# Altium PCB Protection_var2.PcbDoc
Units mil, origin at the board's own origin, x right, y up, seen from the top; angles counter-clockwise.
Board outline 2400 x 1600 mil, 2 copper layers (Top Layer, Bottom Layer), stack 62 mil thick; 54 components, 17 nets, 103 pads, 31 vias.
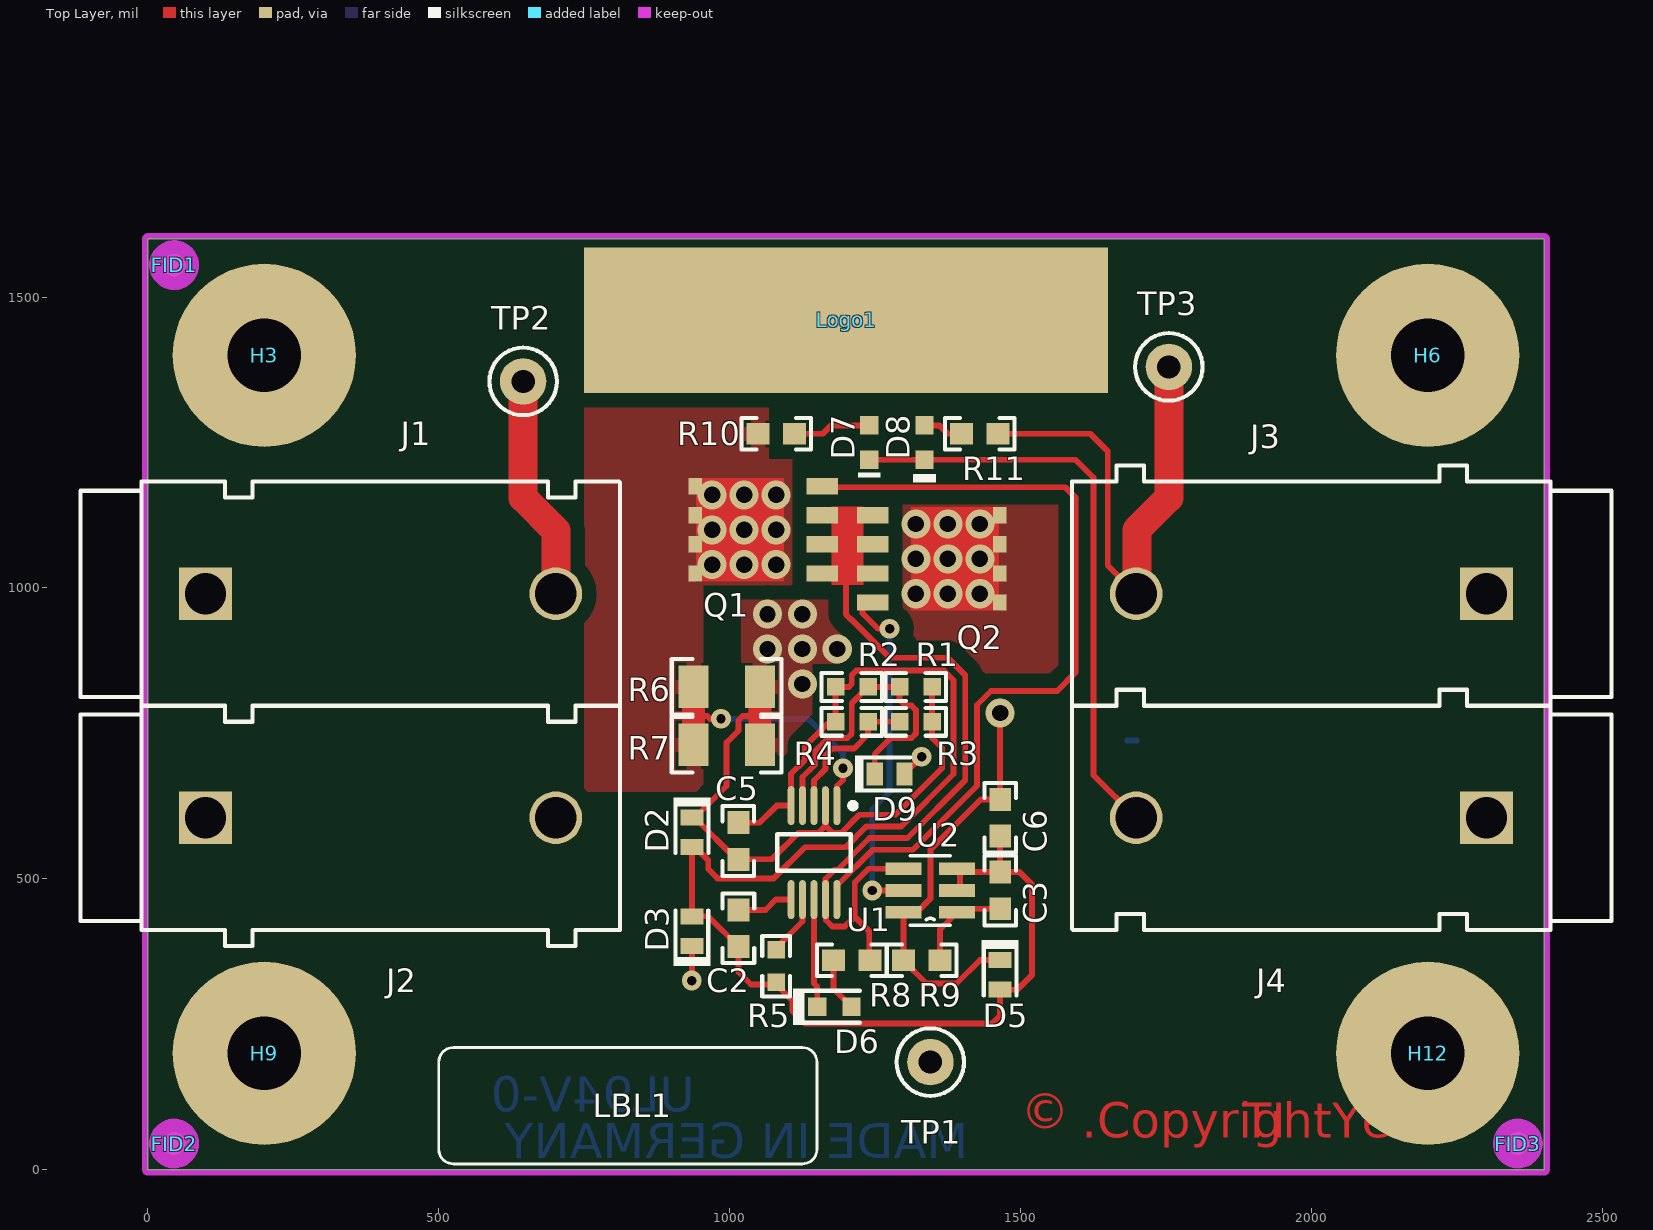
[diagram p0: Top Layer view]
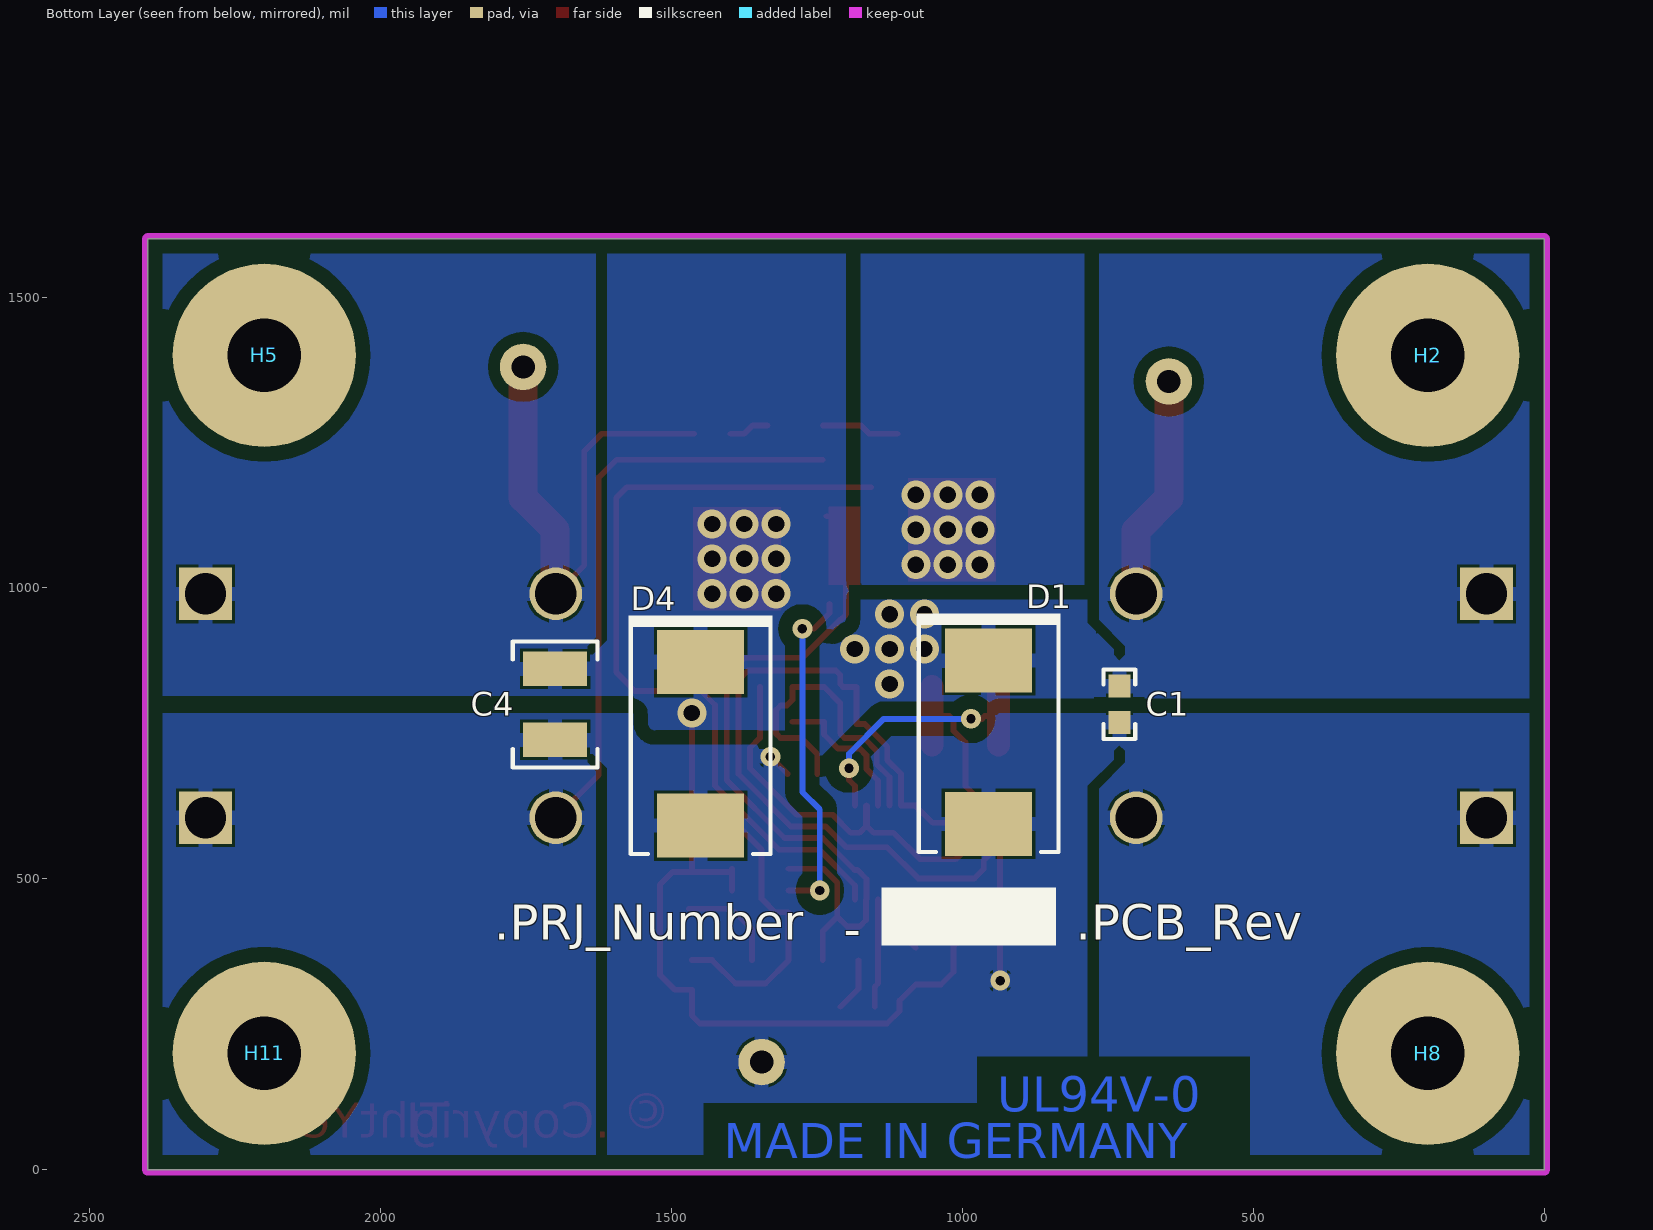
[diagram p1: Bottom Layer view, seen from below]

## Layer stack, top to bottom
Top Layer: signal copper 1.4
Dielectric: core 59.2, FR-4, Dk 4.8
Bottom Layer: signal copper 1.4

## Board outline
0,0 2400,0 2400,1600 0,1600

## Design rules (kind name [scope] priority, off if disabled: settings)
AcuteAngle [All] p1: minimum=4.50000000000000E+0001 checktracksonly=FALSE
AssemblyTestPointUsage [All] p1: valid=2
Clearance Clearance_BoardEdge_MountingHoles [OnCopper and InComponentClass('Mounting Holes') vs IsKeepOut] p1: gap=40
Clearance Clearance_BoardEdge_Poly [OnCopper and InPoly vs IsKeepOut] p2: gap=25
Clearance Clearance_BoardEdge [OnCopper and Not InComponentClass('Logo') and not InComponentClass('FiducialMark') and not InRegion(1000,500,4000,800) and Not IsKeepout vs IsKeepOut] p3: gap=75
Clearance Clearance_Poly [InPolygon] p4: gap=25
Clearance [All] p5: gap=8
ComponentClearance ComponentClearance_Shunt [InComponentClass('Header') vs InComponentClass('Shunt')] p1: gap=0 collisioncheckmode=3 verticalgap=0 showdistances=FALSE
ComponentClearance ComponentClearance_Logo [InComponentClass('Logo')] p2: gap=50 collisioncheckmode=3 verticalgap=10 showdistances=FALSE
ComponentClearance ComponentClearance_ScrewToNut [(HasFootprint('NY PMS 440 0025 PH')) vs (HasFootprint('Keystone_1902C'))] p3: gap=5 collisioncheckmode=3 verticalgap=10 showdistances=FALSE
ComponentClearance ComponentClearance_MountingHoles [InComponentClass('Mounting Holes')] p4: gap=250 collisioncheckmode=3 verticalgap=100000 showdistances=FALSE
ComponentClearance ComponentClearance_SmallPassives [HasFootprint('0201*') or HasFootprint('0402*') or HasFootprint('0508') or HasFootprint('0603*') or HasFootprint('0612') or HasFootprint('0805*') or HasFootprint('0815*') or HasFootprint('0830*') or HasFootprint('1206*') or HasFootprint('1210*') or HasFootprint('1808*') or HasFootprint('1812*') or HasFootprint('1825*') or HasFootprint('2010*') or HasFootprint('2220*') or HasFootprint('2225*') or HasFootprint('2512*') or HasFootprint('2728*') or HasFootprint('3518*') vs HasFootprint('0201*') or HasFootprint('0402*') or HasFootprint('0508') or HasFootprint('0603*') or HasFootprint('0612') or HasFootprint('0805*') or HasFootprint('0815*') or HasFootprint('0830*') or HasFootprint('1206*') or HasFootprint('1210*') or HasFootprint('1808*') or HasFootprint('1812*') or HasFootprint('1825*') or HasFootprint('2010*') or HasFootprint('2220*') or HasFootprint('2225*') or HasFootprint('2512*') or HasFootprint('2728*') or HasFootprint('3518*')] p5: gap=20 collisioncheckmode=3 verticalgap=10 showdistances=FALSE
ComponentClearance ComponentClearance_THtoSMT [IsThruComponent vs IsSMTComponent] p6: gap=100 collisioncheckmode=3 verticalgap=30 showdistances=FALSE
ComponentClearance ComponentClearance_THtoTH [IsThruComponent vs IsThruComponent] p7: gap=118.11 collisioncheckmode=3 verticalgap=30 showdistances=FALSE
ComponentClearance [All] p8: gap=40 collisioncheckmode=3 verticalgap=10 showdistances=FALSE
DiffPairsRouting [All] p1: maxlimit=100 minlimit=10 mostfreqgap=10 maxuncoupledlength=1000
FabricationTestPointUsage TestPointUsage [All] p1: valid=2 allowmultiple=FALSE
FabricationTestpoint Testpoint [All] p1: side=3 testpointundercomponent=TRUE minsize=40 maxsize=100 preferedsize=60 minholesize=0 maxholesize=40 preferedholesize=32 testpointgrid=1 allowsidetop=TRUE allowsidebottom=TRUE usegrid=TRUE gridtolerance=0.01
FanoutControl Fanout_LCC [IsLCC] p1: bgadir=Out bgaviamode=Centered fanoutstyle=Auto fanoutdirection=Alternating viagrid=1 // Fanout_LCC (Default Rule)
FanoutControl Fanout_BGA [IsBGA] p2: bgadir=Out bgaviamode=Centered fanoutstyle=Auto fanoutdirection=Alternating viagrid=1 // Fanout_BGA (Default Rule)
FanoutControl Fanout_Default [All] p4: bgadir=Out bgaviamode=Centered fanoutstyle=Auto fanoutdirection=Alternating viagrid=1 // Fanout_Default (Default Rule)
FanoutControl Fanout_Small [(CompPinCount < 5)] p5: bgadir=Out bgaviamode=Centered fanoutstyle=Auto fanoutdirection=OutThenIn viagrid=1 // Fanout_Small (Default Rule)
HoleSize [All] p1: absolutevalues=TRUE maxlimit=251 minlimit=8 maxpercent=80.000 minpercent=20.000
MinimumAnnularRing MinimumAnnularRing_ThermalPadVias [IsVia and InAnyComponent] p1: minimumring=5.91
MinimumAnnularRing [All] p2: minimumring=9
MinimumSolderMaskSliver MinimumSolderMaskSliver_Logo [InComponentClass('Logo') vs InComponentClass('Logo')] p1: minsoldermaskwidth=0.7
MinimumSolderMaskSliver [All] p2: minsoldermaskwidth=3.94
PlaneConnect [All] p1: planeconnectstyle=Relief reliefexpansion=10 reliefentries=4 reliefconductorwidth=10 reliefairgap=10
PolygonConnect ThermalPolygonQ [(ObjectKind = 'Pad') And (Name Like 'Q*')] p1: connectstyle=Direct reliefconductorwidth=10 reliefentries=4 polygonreliefangle="90 Angle" airgapwidth=10 // Connect Transistor Cooling Pad to Poligon
PolygonConnect ThermalPolygonVia [(ObjectKind = 'Via') And (ViaDiameter = '50')] p2: connectstyle=Direct reliefconductorwidth=10 reliefentries=4 polygonreliefangle="90 Angle" airgapwidth=10
PolygonConnect [All] p3: connectstyle=Relief reliefconductorwidth=25 reliefentries=4 polygonreliefangle="90 Angle" airgapwidth=5
RoutingVias ThermalPadVias [IsVia and InAnyComponent] p1: holewidth=7.87 width=19.68 viastyle="Through Hole" minholewidth=7.87 minwidth=19.68 maxholewidth=12.99 maxwidth=23.62
RoutingVias [All] p2: holewidth=16 width=34 viastyle="Through Hole" minholewidth=7.87 minwidth=26 maxholewidth=40 maxwidth=65
SMDToCorner [All] p1: distance=30000
SilkToSilkClearance [All] p1: silktosilkclearance=5
SilkscreenOverComponentPads [All] p1: minsilkscreentomaskgap=5
SolderMaskExpansion [All] p1: expansion=1.97
Width [All] p1: maxlimit=100 minlimit=6 preferedwidth=10 checkconnectedcopper=TRUE
14 further rules are at their usual default settings.

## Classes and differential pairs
component class Label: LBL1
component class AssemblyNote: ZZ1 ZZ2 ZZ3 ZZ4
component class FiducialMark: FID1 FID2 FID3
component class "Pg4 Hardware": FID1 FID2 FID3 H2 H3 H5 H6 H8 H9 H11 H12 LBL1 Logo1 ZZ1 ZZ2 ZZ3 ZZ4
component class Logo: Logo1
component class "Mounting Holes": H3 H6 H9 H12
component class "Pg3 Protection": C1 C2 C3 C4 C5 C6 D1 D2 D3 D4 D5 D6 D7 D8 D9 J1 J2 J3 J4 Q1 Q2 R1 R2 R3 R4 R5 R6 R7 R8 R9 R10 R11 TP1 TP2 TP3 U1 U2

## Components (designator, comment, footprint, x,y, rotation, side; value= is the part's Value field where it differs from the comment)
C1 "06031C102JAT2A" 0603 730,800 r270 bottom
C2 "UMK107ABJ474KA-T" 0603 1015,415 r270 top
C3 "GRM188R72A104KA35D" 0603 1465,480 r90 top
C4 "C3225X7S2A475K200AB" 1210M 1700,800 r270 bottom
C5 "GRM188R72A104KA35D" 0603 1015,565 r90 top
C6 "GRM188R72A104KA35D" 0603 1465,605 r270 top
D1 "SMCJ33CA" SMC 955,735 r270 bottom
D2 "CD0603-S01575" Diode_0603 935,580 r270 top
D3 "CD0603-S01575" Diode_0603 935,410 r90 top
D4 "SMCJ33CA" SMC 1450,731.97 r270 bottom
D5 "CD0603-S01575" Diode_0603 1465,335 r270 top
D6 "LTST-C190CKT" LED_LTST-C190_Red 1180,280 r180 top
D7 "LB Q39G-L2N2-35-1" "LB Q39G_BLUE" 1240,1250 r270 top
D8 "LTST-C190KGKT" LED_LTST-C190_G 1335,1250 r270 top
D9 "CD0603-S01575" Diode_0603 1275,680 r0 top
FID1 "Fiducial" Fiducial10-20 45,1555 r0 top
FID2 "Fiducial" Fiducial10-20 45,45 r0 top
FID3 "Fiducial" Fiducial10-20 2355,45 r0 top
H2 "1902C" Keystone_1902C 200,1400 r180 bottom locked
H3 "NY PMS 440 0025 PH" "NY PMS 440 0025 PH" 200,1400 r0 top locked
H5 "1902C" Keystone_1902C 2200,1400 r180 bottom locked
H6 "NY PMS 440 0025 PH" "NY PMS 440 0025 PH" 2200,1400 r0 top locked
H8 "1902C" Keystone_1902C 200,200 r180 bottom locked
H9 "NY PMS 440 0025 PH" "NY PMS 440 0025 PH" 200,200 r0 top locked
H11 "1902C" Keystone_1902C 2200,200 r180 bottom locked
H12 "NY PMS 440 0025 PH" "NY PMS 440 0025 PH" 2200,200 r0 top locked
J1 "571-0500" 571-0500 400,990 r0 top
J2 "571-0100" 571-0100 400,605 r0 top
J3 "571-0500" 571-0500 2000,990 r180 top
J4 "571-0100" 571-0100 2000,605 r180 top
LBL1 "Size: 0.65\" x 0.20 \"" Label_650x200 825,110 r0 top
Logo1 "Texas Instruments" TI_Stacked_SolderMask_Small 1200,1460 r0 top
Q1 "CSD18532Q5B" TRANS_NexFET_Q5B 1050,1100 r180 top
Q2 "CSD18532Q5B" TRANS_NexFET_Q5B 1355,1050 r0 top
R1 "CRCW060395K3FKEA" 0603_HV 1320.08,830 r0 top
R2 "CRCW06038K06FKEA" 0603_HV 1210,830 r0 top
R3 "CRCW060347K5FKEA" 0603_HV 1320.08,770 r0 top
R4 "CRCW060314K0FKEA" 0603_HV 1210,770 r0 top
R5 "CRCW060357K6FKEA" 0603_HV 1080,350 r90 top
R6 "WSLP1206R0100FEA" 1206 995,830 r180 top
R7 "WSLP1206R0100FEA" 1206 995,730.2 r180 top
R8 "CRCW060310K0FKEA" 0603 1210,360 r180 top
R9 "CRCW0603100RFKEA" 0603 1330,360 r180 top
R10 "CRCW060310K0FKEA" 0603 1080,1265 r0 top
R11 "CRCW060310K0FKEA" 0603 1430,1265 r180 top
TP1 "5001" Keystone5001 1345,185 r0 top
TP2 "5000" Keystone5000 645,1355 r0 top
TP3 "5000" Keystone5000 1755,1380 r0 top
U1 "LM5069MM-2/NOPB" MUB10A_N 1145,545.12 r270 top
U2 "LM5050MK-1/NOPB" DDC0006A_N 1345,480 r180 top
ZZ1 "This Assembly Note is for PCB labels only" AssemblyNoteLabel -10,3268 r0 top
ZZ2 "These assemblies are ESD sensitive, ESD precautions shall be observed." AssemblyNote -10,3159.11 r0 top
ZZ3 "These assemblies must be clean and free from flux and all contaminants. Use of no clean flux is not acceptable." AssemblyNote -10,3070.56 r0 top
ZZ4 "These assemblies must comply with workmanship standards IPC-A-610 Class 2, unless otherwise specified." AssemblyNote -10,2982 r0 top

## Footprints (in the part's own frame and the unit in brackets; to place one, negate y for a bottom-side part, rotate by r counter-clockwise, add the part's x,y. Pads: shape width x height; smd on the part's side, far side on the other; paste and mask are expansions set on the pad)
571-0100 [mm] "Deltron Emcon recommended land pattern 2003-10-13"
  rect 2.3x2.3 hole 1.8: 1(-7.65,0)
  round 2.3 hole 1.8: 2(7.65,0)
  silkscreen extent -13.1,-5.6 10.45,4.9, body extent -13.04,-5.6 10.54,4.9, height 12.4
571-0500 [mm] "Deltron Emcon recommended land pattern 2003-10-13"
  rect 2.3x2.3 hole 1.8: 1(-7.65,0)
  round 2.3 hole 1.8: 2(7.65,0)
  silkscreen extent -13.1,-5.6 10.45,4.9, body extent -13.04,-5.6 10.54,4.9, height 12.4
0603 [mm] "0603 from SM-752 data"
  rect 1x0.95 smd: 1(-0.8,0) 2(0.8,0)
  silkscreen extent -1.52,-0.69 1.52,0.69, body extent -0.87,-0.47 0.87,0.47, height 0.85
0603_HV [mil] "Ernesto recommended land pattern.  26 mil between pads."
  rect 30x30 smd: 1(-28,0) 2(28,0)
  silkscreen extent -52,-24 52,24, body extent -34,-19 34,19, height 33
1206 [mm] "1206 from SM-752 data"
  rect 1.3x1.85 smd: 1(-1.45,0) 2(1.45,0)
  silkscreen extent -2.4,-1.21 2.4,1.21, body extent -1.7,-0.9 1.7,0.9, height 1.35
1210M [mm] "1210 from SM-752 data"
  rect 1.5x2.8 smd: 1(-1.55,0) 2(1.55,0)
  silkscreen extent -2.75,-1.85 2.75,1.85, body extent -1.7,-1.35 1.7,1.35, height 1.35
AssemblyNote [mil] "Assembly Note"
AssemblyNoteLabel [mil] "Assembly Note for PCB Labels"
DDC0006A_N [mil]
  rect 62x22 smd: 1(-46,37.4) 2(-46,0) 3(-46,-37.4) 4(46,-37.4) 5(46,0) 6(46,37.4)
  silkscreen extent -35,-60 35,60, body extent -56,-58 56,58, height 35
Diode_0603 [mm] "Based on Bourns recommended land pattern Rev 10/09"
  rect 0.7x1 smd: 1(-0.65,0) 2(0.65,0)
  silkscreen extent -1.5,-0.8 0.9,0.8, body extent -0.9,-0.5 0.9,0.5, height 0.85
Fiducial10-20 [mm]
  round 1 smd paste-0.5 mask+0.5: 1(0,0)
  Top Layer keep-out circle w1.178: c0,0 r0.5
Keystone5000 [mil] "For Keystone 500x miniature loop terminals"
  round 80 hole 40: 1(0,0)
  silkscreen extent -58,-58 58,58, body extent -49,-49 49,49, height 182
Keystone5001 [mil] "For Keystone 500x miniature loop terminals"
  round 80 hole 40: 1(0,0)
  silkscreen extent -58,-58 58,58, body extent -49,-49 49,49, height 182
Keystone_1902C [mil] "Hex Standoff, 4-40 threaded, nylon"
  body extent -145,-126 146,126, height 501
Label_650x200 [mil] "Thermal Transfer Label"
  silkscreen extent -325,-100 325,100, body extent -326,-101 326,101, height 1
"LB Q39G_BLUE" [mm] "OSRAM"
  rect 0.8x0.8 smd: 1(-0.75,0) 2(0.75,0)
  silkscreen extent 1.31,-0.5 1.53,0.5, body extent -0.85,-0.45 0.85,0.45, height 0.4
LED_LTST-C190_G [mm] "Lite-On"
  rect 0.8x0.8 smd: 1(-0.75,0) 2(0.75,0)
  silkscreen extent 1.37,-0.5 1.75,0.5, body extent -0.85,-0.45 0.85,0.45, height 0.9
LED_LTST-C190_Red [mm] "Lite-On"
  rect 0.8x0.8 smd: 1(-0.75,0) 2(0.75,0)
  silkscreen extent -1.1,-0.8 1.8,0.8, body extent -0.85,-0.45 0.85,0.45, height 0.9
MUB10A_N [mm] "TSSOP, 10-Leads, Body 3x3mm, Pitch 0.5mm, IPC Medium Density"
  oval 1.7x0.3 smd: 1(-2.05,1) 2(-2.05,0.5) 3(-2.05,0) 4(-2.05,-0.5) 5(-2.05,-1) 6(2.05,-1) 7(2.05,-0.5) 8(2.05,0) 9(2.05,0.5) 10(2.05,1)
  silkscreen extent -2.17,-1.6 0.8,1.83, body extent -1.6,-1.6 1.6,1.6, height 1.09
"NY PMS 440 0025 PH" [mm] "4-40 nylon screw and mounting hole"
  round 8 hole 3.2: 1(0,0)
  body extent -3.3,-3.3 3.3,3.3, height 2.69
SMC [mil] "Molded Diode, 2-Leads, Body 6.9x5.8mm, IPC Medium Density, based on OnSemi component dimensions and land patterns"
  rect 110x150 smd: 1(-140.49,0) 2(140.49,0)
  silkscreen extent -221,-124 189,123, body extent -156,-116 156,116, height 91
TI_Stacked_SolderMask_Small [mil]
  rect 900x250 smd paste-125 mask-125: 0(0,0)
TRANS_NexFET_Q5B [mm] "TI recommended land pattern (nominal) November 2012"
  rect 1.372x0.71 smd paste-0.4 mask+0.051: 1(-2.776,1.905) 2(-2.776,0.635) 3(-2.776,-0.635) 4(-2.776,-1.905)
  rect 0.59x0.71 smd paste-0.3: 5(2.776,-1.905) 6(2.776,-0.635) 7(2.776,0.635) 8(2.776,1.905)
  Top Layer region: -1.106,-2.26 2.744,-2.26 2.744,2.26 -1.106,2.26
  body extent -3.23,-2.55 2.87,2.55, height 1.06

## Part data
C1: "CAP, CERM, 1000pF, 100V, +/-5%, X7R, 0603"
C2: "CAP, CERM, 0.47uF, 50V, 10%, X5R, 0603"
C3 C5 C6: "CAP, CERM, 0.1uF, 100V, +/-10%, X7R, 0603"
C4: "CAP, CERM, 4.7uF, 100V, +/-10%, X7S, 1210"
D1 D4: "Diode, TVS, Bi, 33V, 1500W, SMC"
D2 D3 D5 D9: "Diode, Switching, 100V, 0.15A, 0603 Diode"
D6: "LED, Red, SMD"
D7: "LED, Blue, SMD"
D8: "LED, Green, SMD"
FID1 FID2 FID3: "Fiducial mark.  There is nothing to buy or mount."
H2 H5 H8 H11: "Standoff, Hex, 0.5\"L #4-40 Nylon"
H3 H6 H9 H12: "Machine Screw, Round, #4-40 x 1/4, Nylon, Philips panhead"
J1 J3: "Standard Banana Jack, insulated, 10A, red"
J2 J4: "Standard Banana Jack, insulated, 10A, black"
LBL1: library part THT-14-423-10, "Thermal Transfer Printable Labels, 0.650\" W x 0.200\" H - 10,000 per roll"
Logo1: library part TI_Logo, "Texas Instrument Corporate Signature"
Q1 Q2: "MOSFET, N-CH, 60V, 172A, SON 5x6mm"
R1: "RES, 95.3k ohm, 1%, 0.1W, 0603"
R2: "RES, 8.06k ohm, 1%, 0.1W, 0603"
R3: "RES, 47.5k ohm, 1%, 0.1W, 0603"
R4: "RES, 14.0k ohm, 1%, 0.1W, 0603"
R5: "RES, 57.6k ohm, 1%, 0.1W, 0603"
R6 R7: "RES, 0.01 ohm, 1%, 1W, 1206"
R8 R10 R11: "RES, 10.0k ohm, 1%, 0.1W, 0603"
R9: "RES, 100 ohm, 1%, 0.1W, 0603"
TP1: "Test Point, Miniature, Black, TH"
TP2 TP3: "Test Point, Miniature, Red, TH"
U1: "Positive High Voltage Hot Swap / Inrush Current Controller with Power Limiting, 10-pin MSOP, Pb-Free"
U2: "LM5050-1 High Side OR-ing FET Controller, DDC0006A"
ZZ1: library part AssemblyNoteLabel
ZZ2 ZZ3 ZZ4: library part AssemblyNote

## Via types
v1: diameter 50, hole 28, Top Layer to Bottom Layer, 25 vias
v2: diameter 34, hole 16, Top Layer to Bottom Layer, 6 vias

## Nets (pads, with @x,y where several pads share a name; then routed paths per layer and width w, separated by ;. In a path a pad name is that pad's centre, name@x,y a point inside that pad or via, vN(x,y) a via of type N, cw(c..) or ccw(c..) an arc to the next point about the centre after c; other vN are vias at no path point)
24V_LIM: C4.1 C6.1 D4.1 D5.1 J3.1 J3.2 Q2.5 Q2.6 Q2.7 Q2.8 R9.2 R11.1 TP3.1 U2.6 | length 1791.1
  Top Layer w10: R11.1 1620.05,1265 1650,1235.05 1650,1038.82 J3.2 ; D5.1 1430.59,360.59 1390,320 1338.5,320 R9.2 1299,360.5 U2.6 1321.98,442.6 1345,465.62 1345,550 1431.5,636.5 C6.1 v1(1465,785)
  Top Layer w50: J3.2@1700,995 1700,1100 1755,1155 TP3.1
  Bottom Layer w10: J3.2 J3.2@1700,988.82 ; TP3.1@1785,1380 ccw(c1755,1380) TP3.1@1785,1380
  other v1: 1320,990 1375,990 1430,990 1320,1050 1375,1050 1430,1050 1320,1110 1375,1110 1430,1110
+24V: C1.1 C5.1 D1.1 D2.1 J1.1 J1.2 R1.2 R3.2 R6.1 R7.1 TP2.1 U1.2 | length 1665.3
  Top Layer w10: D2.1 939.41,605.59 1011.5,533.5 C5.1 1072.36,533.5 1118.22,579.36 1152.83,579.36 1163.91,590.44 1163.91,625.05 U1.2 1165.46,625.05 1165.46,590.44 1176.54,579.36 1192.2,579.36 1222.84,610 1285,610 1365,690 1365,725 1348.08,741.92 R3.2 R1.2 ; D2.1@940.59,605.59 994.41,659.41 994.41,734.08 1015,754.67 1015,772.57 1022.52,780.1 1052.09,780.1
  Top Layer w40: R7.1 1052.09,780.1 R6.1
  Top Layer w50: TP2.1 645,1155 701.18,1098.82 J1.2
  Bottom Layer w10: TP2.1@675,1355 ccw(c645,1355) TP2.1@675,1355
  other v1: 1125,835 1065,895 1125,895 1185,895 1065,955 1125,955
GND: C1.2 C4.2 D1.2 D3.1 D4.2 D7.2 D8.2 D9.2 J2.1 J2.2 J4.1 J4.2 TP1.1 | length 1131.9
  Top Layer w10: v2(935,325) D3.1 ; D7.2 D8.2 1594.53,1220.47 1625.2,1189.8 1625.2,678.62 J4.2 ; D9.2 1300.59,680.59 v2(1330,710)
  Bottom Layer w10: C4.2@1682.91,737.91 C4.2@1700,737.91
NetC2_1: C2.1 U1.6 | length 98.1
  Top Layer w10: C2.1 1061.5,446.5 1079.41,464.41 U1.6
NetC2_2: C2.2 C3.2 C5.2 C6.2 D2.2 D3.2 D5.2 R2.1 R4.1 R5.1 U1.5 U2.2 U2.3 | length 2553.8
  Top Layer w10: D3.2 962.91,435.59 C2.2 1015,340 1036.5,318.5 1080,318.5 1107.82,290.68 1107.82,272.77 1129.34,251.25 1451.25,251.25 1465,265 D5.2 1494.41,309.41 1520,335 1520,490 1498.5,511.5 C3.2 ; D3.2@935,440.71 D2.2 940.59,554.41 963.06,531.94 963.06,516.94 979.18,500.82 1075.82,500.82 1129.41,554.41 1199.41,554.41 1235,590 1295,590 1385,680 1385,841.46 1368.46,858 1217.62,858 1210,850.38 1210,835 1205,830 R2.1 R4.1 1182,766 1167.66,766 1129,727.34 1129,704 1105.63,680.63 U1.5 1080.83,625.83 1051.5,596.5 C5.2 ; U2.2@1396,480 U2.3@1396,510 ; U2.3@1396,517.4 U2.3@1396,510 ; C6.2 C3.2 ; U2.3@1396,510 1397.5,511.5 C3.2
NetC3_1: C3.1 R9.1 U2.1 | length 162.9
  Top Layer w10: R9.1 1361.5,413.09 U2.1 ; U2.1@1401.91,448.5 C3.1 C3.1@1470,448.5
NetD6_1: D6.1 R8.2 | length 92.9
  Top Layer w10: R8.2 1178.5,311.02 D6.1
NetD6_2: D6.2 U1.8 | length 186.7
  Top Layer w10: U1.8 1145,320 1150.47,314.53 D6.2
NetD7_1: D7.1 R10.2 | length 134.5
  Top Layer w10: R10.2 1160,1265 1174.53,1279.53 D7.1
NetD8_1: D8.1 R11.2 | length 69.5
  Top Layer w10: D8.1 1360.47,1279.53 1375,1265 R11.2
NetD9_1: D9.1 R1.1 R2.2 U1.4 | length 542.2
  Top Layer w10: U1.4 1125.32,674.86 1147,696.54 1147,719.88 1169.12,742 1202.38,742 1210,749.62 1210,802 R2.2 R1.1 1292.08,807.92 1302,798 1312.46,798 1320.08,790.38 1320.08,749.62 1312.46,742 1277,742 1249.41,714.41 D9.1
NetQ1_1: Q1.1 Q1.2 Q1.3 Q2.1 Q2.2 Q2.3 R8.1 U1.9 U2.4 | length 1184.3
  Top Layer w10: 1190,1020 1200,1010 1200,955 1200.65,954.35 1200.65,953.63 1208.27,946.02 1208.98,946.02 1275,880 1375,880 1405,850 1405,669.27 1305.73,570 1240.46,570 1185.46,515 1180,515 1164.69,499.69 U1.9 1165.46,463.63 1165.46,429.02 1176.54,417.95 1197.95,417.95 1215,435 ; Q2.1@1228.41,1123.29 Q2.1@1233.36,1123.29 ; R8.1@1240,360 1240,410 1215,435 ; U2.4 1238.77,517.4 1215,493.63 1215,435
NetQ1_4: Q1.4 U1.10 | length 1413.3
  Top Layer w10: Q1.4@1157.02,1173.29 1576.71,1173.29 1595,1155 1595,855 1563,823 1449.26,823 1425,798.74 1425,660 1315,550 1245.91,550 1184.37,488.46 U1.10
NetQ1_5: Q1.5 Q1.6 Q1.7 Q1.8 R6.2 R7.2 R10.1 U1.1 | length 477.4
  Top Layer w10: 937.91,780 961.46,780 966.46,775 v2(985,775) ; U1.1 1184.37,659.37 1195,670 v2(1195,690)
  Top Layer w40: R7.2 937.91,780 R6.2
  Bottom Layer w10: v2(985,775) 1135,775 1195,715 v2(1195,690)
  other v1: 970,1040 1025,1040 1080,1040 970,1100 1025,1100 1080,1100 970,1160 1025,1160 1080,1160
NetQ2_4: Q2.4 U2.5 | length 599.7
  Top Layer w10: Q2.4@1228.41,972.3 1228.41,956.59 1255,930 v2(1275,930) ; v2(1245,480) U2.5
  Bottom Layer w10: v2@1245,470 v2(1245,480) 1245,619.4 1275,649.4 v2(1275,930)
NetR3_1: R3.1 R4.2 U1.3 | length 258.7
  Top Layer w10: U1.3 1145,669.09 1165,689.09 1165,712.43 1176.57,724 1214,724 1238,748 R4.2 R3.1
NetR5_2: R5.2 U1.7 | length 101.7
  Top Layer w10: R5.2@1080,381.5 1125.32,426.81 U1.7
pads on no net: FID1.1 FID2.1 FID3.1 H3.1 H6.1 H9.1 H12.1 Logo1.0

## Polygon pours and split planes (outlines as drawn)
24V_LIM on Top Layer "Top Layer-No Net 3" (solid, pour order 12): 1275,1150 1275,823 1610,823 1610,1150
NetQ1_5 on Top Layer "Top Layer-No Net 2" (solid, pour order 13): 750,1310 750,954.62 750,650 1170,650 1170,1310
+24V on Top Layer "Top Layer-No Net" (solid, pour order 15): 995,650 1200,650 1200,980 995,980
NetQ1_5 on Bottom Layer "Top Layer-No Net 1" (solid, pour order 3): 765,1005 765,1585 1175,1585 1175,1005
+24V on Bottom Layer "Bottom Layer-No Net" (solid, pour order 5): 15,1585 15,810 776.72,810 776.72,1574.08 780,1585
+24V on Bottom Layer "Bottom Layer-No Net 1" (solid, pour order 7): 770.44,710 770.44,978.82 774.93,980 1275,980 1275,710
GND on Bottom Layer "Bottom Layer-No Net 2" (solid, pour order 17): 15,785 15,15 1245,15 1245,785
24V_LIM on Bottom Layer "Bottom Layer-No Net 3" (solid, pour order 19): 1175,755.53 1175,1585 1550,1585 1550,755
GND on Bottom Layer "Bottom Layer-No Net 4" (solid, pour order 21): 1245,15 1245.02,15.03 1600,15.03 1600,790 1245,790
GND on Bottom Layer "Bottom Layer-No Net 5" (solid, pour order 25): 1590,15 2385,15 2385,805 1590,805
24V_LIM on Bottom Layer "Bottom Layer-No Net 6" (solid, pour order 27): 2385,800 2385,1585 1540,1585 1540,800

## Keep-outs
Keep-Out Layer:
  lines w10: -5,0 ccw(c0,0) 0,-5 ; -5,0 ccw(c0,0) 0,-5 ; -5,0 -5,1600 ; -5,1600 cw(c0,1600) 0,1605 ; -5,1600 cw(c0,1600) 0,1605 ; 0,-5 2400,-5 ; 0,1605 2400,1605 ; 2400,-5 ccw(c2400,0) 2405,0 ; 2400,-5 ccw(c2400,0) 2405,0 ; 2400,1605 cw(c2400,1600) 2405,1600 ; 2400,1605 cw(c2400,1600) 2405,1600 ; 2405,0 2405,1600
  text ".Layer_Name" at 577,-858.49 h60

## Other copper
Top Layer:
  rectangle net NetQ1_1: 1175,1005 1230,1140
  pour cut-out: 955,1005 955,660 1020,660 1020,1005
  pour cut-out: 1020,1005 1130,1005 1130,1000 1020.04,1000 1020,999.96
  text ".CopyrightYear" at 1605,55 h60
  text "TI" at 1881,55 h60
  text "©" at 1500,50 h105
  text ".Layer_Name" at 577,-858.49 h60
Bottom Layer:
  pour cut-out: 1565,815 1565.49,785 2385,785 2385,815
  pour cut-out: 1610,1585 1630.26,1585 1630.02,964.65 1630,915 1645,900 1645,885 1635,885 1610,910
  pour cut-out: 1610,15 1610,690 1635,715 1645,715 1645,700 1630,685 1630,15
  pour cut-out: 740,885 730,875 720,885 720,900 765,945 765,1585 785,1585 785,940 740,895
  pour cut-out: 765,20 785,20 785,660 740,705 740,720 730,730 720,720 720,700 765,655
  text "UL94V-0" at 940,100 h60
  text "MADE IN GERMANY" at 1410,20 h60
  text ".VersionControl_RevNumber" at 4850,-40 h60
  text "SVN:" at 5070,-40 h60
  text ".Layer_Name" at 577,-858.49 h60

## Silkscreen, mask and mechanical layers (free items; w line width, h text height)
Top Overlay:
  text ".Layer_Name" at 577,-858.49 h60
Bottom Overlay:
  rectangle: 839,385 1139,485
  text ".PCB_Rev" at 805,395 h60
  text ".PRJ_Number" at 1805,395 h60
  text "-" at 1204,384.5 h60
  text ".Layer_Name" at 577,-858.49 h60
Top Paste:
  text ".Layer_Name" at 577,-858.49 h60
Bottom Paste:
  text ".Layer_Name" at 577,-858.49 h60
Top Solder:
  text ".Layer_Name" at 577,-858.49 h60
  text ".Layer_Name" at 577,-858.49 h60
Bottom Solder:
  text ".Layer_Name" at 577,-858.49 h60
Drill Guide:
  text ".Layer_Name" at 577,-858.49 h60
M1 Board Outline:
  the board outline again, w10
  text ".Layer_Name" at 577,-858.49 h60
M2 Board Dimensions:
  rectangle: 124.5,-410.5 499.5,-285.5
  rectangle: -0.5,-285.5 124.5,-160.5
  lines w7: -0.5,-285.5 999.5,-285.5 ; 124.5,-410.5 124.5,-160.5 ; 249.5,-410.5 249.5,-160.5 ; 499.5,-410.5 499.5,-160.5 ; 749.5,-410.5 749.5,-160.5 ; -0.5,-410.5 -0.5,-160.5 999.5,-160.5 999.5,-410.5 -0.5,-410.5
  lines w10: -0.5,-475.5 -0.5,-455.5 ; 59.5,-485.5 -0.5,-465.5 ; 59.5,-445.5 -0.5,-465.5 ; 223.58,-465.5 -0.5,-465.5 ; 775.42,-465.5 999.5,-465.5 ; 939.5,-485.5 999.5,-465.5 ; 939.5,-445.5 999.5,-465.5 ; 999.5,-475.5 999.5,-455.5
  text "1000 (mil)" at 233.58,-501.49 h60
  text ".Layer_Name" at 577,-858.49 h60
M3 3D STEP Top:
  text ".Layer_Name" at 577,-858.49 h60
M4 3D STEP Bottom:
  text ".Layer_Name" at 577,-858.49 h60
M5 Assembly Top:
  lines w10: -292,-930.17 6308,-930.17 ; -292,-726.83 6310,-726.83 ; -292,-523.5 -292,-1133.5 3713,-1133.5 6310,-1133.5 6310,-523.5 -291.5,-523.5 -291.5,-1133.5 1284,-1133.5 ; 2173,-1133.5 2173,-523.5 ; 3440,-726.83 3440,-523.5 ; 4280,-726.83 4280,-523.5 ; 4902,-1140 4902,-937.17
  text "COMPONENTS MARKED 'DNP' SHOULD NOT BE POPULATED." at 1153.5,-318.5 h60
  text "ASSEMBLY VARIANT:" at 1153,-434 h60
  text ".VariantName" at 2189,-434 h60
  text "PCB VIEWED FROM TOP SIDE" at -228.5,-655.67 h60
  text "BOARD #:" at 2248,-655.67 h60
  text ".PRJ_Number" at 2793.5,-655.67 h60
  text "REV:" at 3638,-655.67 h60
  text ".PCB_Rev" at 3929.5,-655.67 h60
  text "SVN REV:" at 4476,-655.67 h60
  text ".VersionControl_RevNumber" at 4982,-655.67 h60
  text "IGNORE ->" at -228.5,-858.49 h60
  text "PLOT NAME =" at -228.5,-1064.34 h60
  text ".plot_File_Name" at 577,-1064.34 h60
  text "GENERATED    :" at 2250,-1064.34 h60
  text ".Print_Date" at 3119.5,-1064.34 h60
  text ".Print_Time" at 3848.5,-1064.34 h60
  text "TEXAS INSTRUMENTS" at 5113,-1064.34 h60
M6 Assembly Bottom:
  lines w10: -292.5,-727.33 6309.5,-727.33 ; -290.5,-930.67 6309.5,-930.67 ; 1115.5,-1140.5 1115.5,-937.67 ; 1737.5,-727.33 1737.5,-524 ; 2577.5,-727.33 2577.5,-524 ; 3844.5,-1134 3844.5,-524 ; 4733.5,-1134 6309,-1134 6309,-524 -292.5,-524 -292.5,-1134 2304.5,-1134 6309.5,-1134 6309.5,-524
  text "COMPONENTS MARKED 'DNP' SHOULD NOT BE POPULATED." at 6102,-318 h60
  text ".VariantName" at 5058,-434 h60
  text "ASSEMBLY VARIANT:" at 6097,-434 h60
  text ".VersionControl_RevNumber" at 1035.5,-656.17 h60
  text "SVN REV:" at 1541.5,-656.17 h60
  text ".PCB_Rev" at 2088,-656.17 h60
  text "REV:" at 2379.5,-656.17 h60
  text ".PRJ_Number" at 3224,-656.17 h60
  text "BOARD #:" at 3769.5,-656.17 h60
  text "PCB VIEWED FROM BOTTOM SIDE" at 6246,-656.17 h60
  text "IGNORE ->" at 2547.85,-858.49 h60
  text "TEXAS INSTRUMENTS" at 904.5,-1064.84 h60
  text ".Print_Time" at 2169,-1064.84 h60
  text ".Print_Date" at 2898,-1064.84 h60
  text "GENERATED    :" at 3767.5,-1064.84 h60
  text ".plot_File_Name" at 5440.5,-1064.84 h60
  text "PLOT NAME =" at 6246,-1064.84 h60
M9 Title Sheet:
  drawing of 55 lines, arcs and shapes, not listed
  text "4" at 8231.51,8036.5 h70
  text "5" at 10730.5,8036.5 h70
  text "6" at 13235.5,8036.5 h70
  text "A" at -416.5,6893.5 h70
  text "A" at 14383.5,6893.5 h70
  text "B" at -416.5,4513.5 h70
  text "B" at 14383.5,4513.5 h70
  text "C" at -416.5,2138.5 h70
  text "C" at 14383.5,2138.5 h70
  text "PROJECT TITLE:" at 11343.5,277.5 h45
  text ".PRJ_Title" at 11393.5,144.17 h70
  text "DESIGNED FOR:" at 11343.5,-23.5 h45
  text ".PRJ_Customer" at 11393.5,-163.5 h70
  text "D" at -416.5,-231.5 h70
  text "D" at 14383.5,-231.5 h70
  text "FILE NAME:" at 11343.5,-323.5 h45
  text ".PCB_File_Name_No_Path" at 11393.5,-443.5 h70
  text "Texas Instruments (TI) and/or its licensors do not warrant the accuracy or completeness of this specification" at 6374,-605.34 h45
  text "ENGINEER:" at 11343.5,-613.5 h45
  text "LAYOUT BY:" at 12848.5,-613.5 h45
  text "or any information contained therein. TI and/or its licensors do not warrant that this design will meet" at 6329.01,-718 h45
  text ".PRJ_Engineer" at 11393.5,-768.49 h70
  text ".PCB_Layout" at 12899,-768.49 h70
  text "the specifications, will be suitable for your application or fit for any particular purpose, or will operate in" at 6329.01,-830.67 h45
  text ".Layer_Name" at 577,-858.49 h60
  text "ALTIUM DESIGNER VERSION:" at 12848.5,-923.5 h45
  text "an implementation. TI and/or its licensors do not warrant that the design is production worthy. You should" at 6329.01,-943.33 h45
  text "completely validate and test your design implementation to confirm the system functionality for your application." at 6374,-1056 h45
  text ".print_Scale" at 11393.5,-1056.83 h70
  text ".Application_BuildNumber" at 12899,-1056.83 h70
  text "1" at 739.84,-1263.5 h70
  text "2" at 3235.5,-1263.5 h70
  text "3" at 5724.84,-1263.5 h70
  text "4" at 8231.51,-1263.5 h70
  text "5" at 10730.5,-1263.5 h70
  text "6" at 13235.5,-1263.5 h70
M10 Fab Notes:
  drawing of 212 lines, arcs and shapes, not listed
  text "DESIGN INFORMATION" at 12381.02,6810 h60
  text "(REFER ALSO ARRAY/PANEL PROFILING INFORMATION)" at 12019.46,6648.29 h60
  text "BOARD SIZE" at 11333.46,6644 h60
  text "3450MIL" at 11795.78,6516.18 h60
  text "X" at 12301.46,6516.18 h60
  text "4950MIL" at 12532.78,6516.18 h60
  text "Number of Layers :" at 11736.46,6319 h60
  text "2" at 12831.27,6309 h60
  text "MIN. TRACK WIDTH:" at 11736.46,6180 h60
  text "8" at 12832.7,6180 h60
  text "MIL" at 12987.46,6180 h60
  text "MIN. CLEARANCE:" at 11736.46,6048 h60
  text "8" at 12832.7,6048 h60
  text "MIL" at 12987.46,6048 h60
  text "MIN. VIA PAD SIZE:" at 11736.46,5916 h60
  text "24" at 12802.71,5916 h60
  text "MIL" at 12987.46,5916 h60
  text "0.05mm (2MIL)" at 12431.46,5774.29 h60
  text "MINIMUM ANNULAR RING" at 11407.23,5770 h60
  text "EXTERNAL" at 13139.46,5770 h60
  text "PER" at 11607.23,5652 h60
  text "IPC-D-275 CLASS 2 LEVEL C" at 11827.23,5652 h60
  text "MIL, HOLES" at 13315.46,5539.71 h60
  text "+/-" at 12923,5539 h60
  text "+/-" at 13777,5539 h60
  text "REGISTRATION TOLERANCES:" at 11407.23,5534 h60
  text "METAL" at 12607,5534 h60
  text "5" at 13183.2,5534 h60
  text "3" at 14016.2,5534 h60
  text "MIL" at 14132.46,5534 h60
  text "MATERIAL:" at 11332.46,5324.54 h60
  text "FR-4 High Tg" at 12318.9,5184.21 h60
  text "FR-408" at 11753.46,5175.64 h60
  text "X" at 12165.46,5175.64 h60
  text "OTHER" at 13241.46,5175.64 h60
  text "62 MIL (1.6mm) +/-10%" at 12073.56,5012.92 h60
  text "THICKNESS:" at 11407.23,5008.64 h60
  text "X" at 11945.4,5008.64 h60
  text "OTHER" at 13358.46,5008.64 h60
  text "TOLERANCE:" at 11407.23,4850.64 h60
  text "X" at 12246.53,4850.64 h60
  text "ANSI IPC-6012 TYPE 3 CLASS 2" at 12433.48,4850.64 h60
  text "OTHER +/-" at 12433.46,4694.64 h60
  text "BOW & TWIST:" at 11407.23,4537.64 h60
  text "X" at 12246.53,4537.64 h60
  text "ANSI IPC-6012 TYPE 3 CLASS 2" at 12433.48,4537.64 h60
  text "OTHER +/-" at 12433.46,4379.13 h60
  text "COPPER THICKNESS (FINISHED):" at 11332.46,4243.64 h60
  text "1.4MIL (1oz)" at 12212.46,4090.92 h60
  text "2MIL (1.4oz)" at 12979.46,4090.92 h60
  text "2.8MIL (2oz)" at 13706.46,4090.92 h60
  text "OUTER:" at 11689.46,4086.64 h60
  text "X" at 12084,4086 h60
  text "1.4MIL (1oz)" at 12212.46,3933.92 h60
  text "2.8MIL (2oz)" at 12979.46,3933.92 h60
  text "N/A" at 13706,3934.29 h60
  text "INNER SIGNAL:" at 11400.38,3929.64 h60
  text "X" at 12085.42,3929.64 h60
  text "DRILLING:" at 11332.46,3790.64 h60
  text "REFERENCE:" at 11407.23,3673.64 h60
  text "X" at 12055.46,3673.64 h60
  text "AS SHOWN" at 12242.46,3673.64 h60
  text "X" at 12956.46,3673.64 h60
  text "NC_DRILL FILES" at 13093.46,3673.64 h60
  text "PTH MIN COPPER THICKNESS:" at 11407.23,3515.64 h60
  text "X" at 12757.46,3515.64 h60
  text "1MIL" at 12894.46,3515.64 h60
  text "OTHER" at 13391.46,3515.64 h60
  text "BOARD FINISH:" at 11332.46,3356.64 h60
  text "SILKSCREEN:" at 11487.68,3238.64 h60
  text "X" at 12436.46,3238.64 h60
  text "TOP" at 12562.46,3238.64 h60
  text "X" at 12946.46,3238.64 h60
  text "BOTTOM" at 13073.46,3238.64 h60
  text "SILKSCREEN COLOR:" at 11487.68,3071.64 h60
  text "X" at 12435.42,3071.64 h60
  text "WHITE" at 12562.46,3071.64 h60
  text "OTHER" at 13073.46,3071.64 h60
  text "SOLDER RESIST COLOR:" at 11487.68,2901.64 h60
  text "X" at 12055.42,2742.44 h60
  text "GREEN" at 12182.46,2742.44 h60
  text "BLUE" at 12773.46,2742.44 h60
  text "OTHER" at 13311.46,2742.44 h60
  text "IMMERSION GOLD (ENIG)" at 12393.46,2553.92 h60
  text "ENEPIG" at 13731,2550.64 h60
  text "SURFACE FINISH:" at 11332.46,2549.64 h60
  text "X" at 12206.51,2549.64 h60
  text "IMM. TIN/SILVER OR EQUIV" at 11662,2392.64 h60
  text "OTHER" at 13093.46,2392.64 h60
  text "ARRAY/PANEL:" at 11332.46,2213.64 h60
  text "CUT AND TRIM PER MECH LAYER 1" at 12393.46,2209.35 h60
  text "N.C. ROUTE" at 12393.46,2057.64 h60
  text "X" at 13072.46,2057.64 h60
  text "V. SCORE" at 13259.46,2057.64 h60
  text "CERTIFICATION:" at 11332.46,1920.64 h60
  text "MATERIALS AND WORKMANSHIP FOR ALL PCBS" at 12057.46,1920.64 h60
  text "TO MEET OR EXCEED THE REQUIREMENTS OF:" at 12057.46,1822.64 h60
  text "X" at 11683.96,1686.13 h60
  text "ANSI IPC-A-600F CLASS ->" at 11822.96,1686.13 h60
  text "X" at 13462.02,1686.13 h60
  text "2" at 13580.96,1686.14 h60
  text "1" at 13265.96,1684.64 h60
  text "3" at 13934.96,1684.64 h60
  text "X" at 11686.02,1526.64 h60
  text "UL 94V-0" at 11822.96,1526.64 h60
  text "X" at 12498.02,1526.64 h60
  text "RoHS" at 12634.96,1526.64 h60
  text "OTHER" at 13279.36,1526.64 h60
  text "PER ORDER" at 13676.42,1526.64 h60
  text "ADDITIONAL REQUIREMENTS:" at 11332.46,1385.64 h60
  text "MICROSECTION:" at 11407.23,1270.64 h60
  text "YES" at 12312.96,1270.64 h60
  text "REQUIRED" at 13174.46,1114.49 h60
  text "BARE BOARD ELEC. TEST:" at 11407.23,1111.64 h60
  text "NONE" at 12712.96,1111.64 h60
  text "X" at 13047.46,1111.64 h60
  text "PER ORDER" at 13766.46,1111.64 h60
  text "MANUFACTURER'S UL:" at 11407.23,954.64 h60
  text "RAIL" at 12572.96,950.35 h60
  text "METAL" at 13064.77,950.35 h60
  text "X" at 13440,950 h60
  text "SILK" at 13576.46,950.35 h60
  text ".Layer_Name" at 577,-858.49 h60
M11 Gerber Information:
  lines w10: -292,-930.17 6308,-930.17 ; -292,-726.83 6310,-726.83 ; -292,-523.5 -292,-1133.5 3713,-1133.5 6310,-1133.5 6310,-523.5 -291.5,-523.5 -291.5,-1133.5 1284,-1133.5 ; 2173,-1133.5 2173,-523.5 ; 3440,-726.83 3440,-523.5 ; 4280,-726.83 4280,-523.5 ; 4902,-1140 4902,-937.17
  text "ALL ARTWORK VIEWED FROM TOP SIDE" at -228.5,-655.67 h60
  text "BOARD #:" at 2248,-655.67 h60
  text ".PRJ_Number" at 2793.5,-655.67 h60
  text "REV:" at 3638,-655.67 h60
  text ".PCB_Rev" at 3929.5,-655.67 h60
  text "SVN REV:" at 4476,-655.67 h60
  text ".VersionControl_RevNumber" at 4982,-655.67 h60
  text "LAYER NAME =" at -228.5,-858.49 h60
  text "PLOT NAME =" at -228.5,-1064.34 h60
  text ".plot_File_Name" at 577,-1064.34 h60
  text "GENERATED    :" at 2250,-1064.34 h60
  text ".Print_Date" at 3119.5,-1064.34 h60
  text ".Print_Time" at 3848.5,-1064.34 h60
  text "TEXAS INSTRUMENTS" at 5113,-1064.34 h60
M12 Stackup:
  lines w6: 11360,7460 13910,7460 ; 11360,7564.4 13910,7564.4 ; 11300,6975 ccw(c11334,6975) 11334,6941 13936,6941 ccw(c13936,6975) 13970,6975 13970,7681 ccw(c13936,7681) 13936,7715 11334,7715 ccw(c11334,7681) 11300,7681 11300,6975
  text "The Stackup Legend below this is static." at 11605.5,7874.5 h60
  text "If you change the stackup, update the Legend." at 11615.5,7784.5 h60
  text "Layer Stack Up Detail for: Ref_Design.PcbDoc" at 11360,7597.1 h57
  text "Layer" at 11360,7525.4 h24
  text "Gerber" at 12255.81,7525.4 h24
  text "Copper" at 12819.33,7525.4 h24
  text "Dielectric" at 13422.04,7525.4 h24
  text "Name" at 11360,7477.4 h24
  text "Document" at 12255.81,7477.4 h24
  text "Thickness" at 12819.33,7477.4 h24
  text "Material" at 13422.04,7477.4 h24
  text "Top Solder Mask" at 11360,7384.44 h34
  text "(.GTS)" at 12255.81,7384.44 h34
  text "Solder Resist" at 13422.04,7384.44 h34
  text "Top Layer" at 11360,7287.69 h34
  text "(.GTL)" at 12255.81,7287.69 h34
  text "1.4mil" at 12819.33,7287.69 h34
  text "FR-4" at 13422.04,7239.31 h34
  text "Bottom Layer" at 11360,7190.94 h34
  text "(.GBL)" at 12255.81,7190.94 h34
  text "1.4mil" at 12819.33,7190.94 h34
  text "Bottom Solder Mask" at 11360,7094.19 h34
  text "(.GBS)" at 12255.81,7094.19 h34
  text "Solder Resist" at 13422.04,7094.19 h34
  text ".Layer_Name" at 577,-858.49 h60
M13 Component Bodies Top:
  text ".Layer_Name" at 577,-858.49 h60
M14 Component Bodies Bottom:
  text ".Layer_Name" at 577,-858.49 h60
M15 Courtyards Top:
  text ".Layer_Name" at 577,-858.49 h60
M16 Courtyards Bottom:
  text ".Layer_Name" at 577,-858.49 h60
Drill Drawing:
  text ".legend" at 2605,690 h60
  text "Drill Table" at 2615,525 h60
  text ".Layer_Name" at 577,-858.49 h60

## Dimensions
0,0 to 2400,0 on M2 Board Dimensions
0,0 to 0,1600 on M2 Board Dimensions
